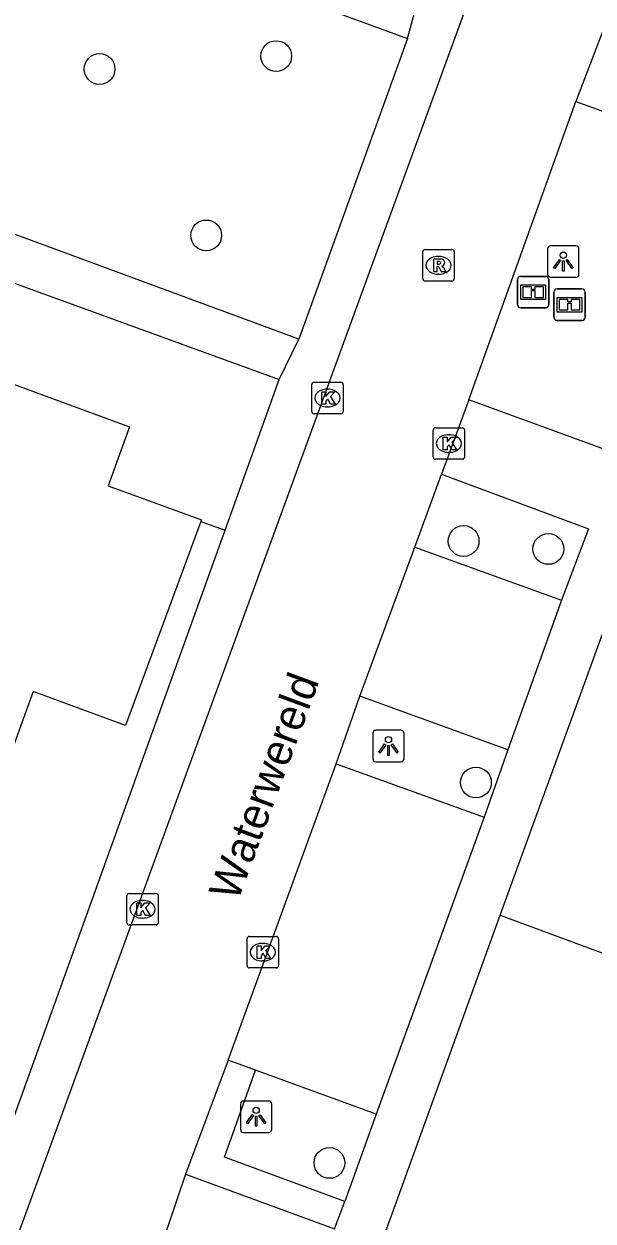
# Model space of a CAD drawing. Extents: x 155275 to 156263, y 382654 to 383635.
# Drawn here: x 155990.1 to 156008.18, y 383082.31 to 383120.33 of the extents above; entities that cross this region are included whole.
import ezdxf

# ---------------------------------------------------------------- set-up
doc = ezdxf.new("R2010")
doc.units = 0
for name, color, linetype in [('IMGEO_Boom', 7, 'Continuous'), ('IMGEO_Hek', 7, 'Continuous'), ('IMGEO_Informatiebord', 7, 'Continuous'), ('IMGEO_Kolk', 7, 'Continuous'), ('IMGEO_Lichtpunt', 7, 'Continuous'), ('IMGEO_Openbare_ruimte_label', 7, 'Continuous'), ('IMGEO_Pand', 7, 'Continuous'), ('IMGEO_Parkeervlak_open', 7, 'Continuous'), ('IMGEO_Rijbaan_lokaal_open', 7, 'Continuous'), ('IMGEO_Rioolput', 7, 'Continuous'), ('IMGEO_Voetpad_open', 7, 'Continuous')]:
    doc.layers.add(name, color=color, linetype=linetype)

msp = doc.modelspace()

# ---------------------------------------------------------------- linework, layer by layer
at = {"layer": 'IMGEO_Boom'}
for centre in [(155998.115, 383119.307), (155992.502, 383118.896), (155995.89, 383113.612), (156004.069, 383103.904), (156006.762, 383103.654), (156004.461, 383096.235), (155999.806, 383084.153)]:
    msp.add_circle(centre, 0.489, dxfattribs=at)
at = {"layer": 'IMGEO_Hek'}
for points in [[(155989.784, 383085.63), (155996.489, 383104.253)], [(155995.721, 383104.53), (155996.489, 383104.253)]]:
    msp.add_lwpolyline(points, dxfattribs=at)
at = {"layer": 'IMGEO_Informatiebord'}
for p, q in [((156005.787, 383111.411), (156005.787, 383112.211)), ((156005.787, 383112.211), (156005.787, 383111.411)), ((156005.887, 383112.311), (156006.677, 383112.311)), ((156006.677, 383112.311), (156005.887, 383112.311)), ((156006.777, 383112.211), (156006.777, 383111.411)), ((156006.777, 383111.411), (156006.777, 383112.211)), ((156006.937, 383111.011), (156006.937, 383111.811)), ((156006.937, 383111.811), (156006.937, 383111.011)), ((156007.037, 383111.911), (156007.827, 383111.911)), ((156007.827, 383111.911), (156007.037, 383111.911)), ((156007.927, 383111.811), (156007.927, 383111.011)), ((156007.927, 383111.011), (156007.927, 383111.811)), ((156006.677, 383111.311), (156005.887, 383111.311)), ((156005.887, 383111.311), (156006.677, 383111.311)), ((156007.827, 383110.911), (156007.037, 383110.911)), ((156007.037, 383110.911), (156007.827, 383110.911))]:
    msp.add_line(p, q, dxfattribs=at)
for points in [[(156005.888, 383112.043), (156006.676, 383112.043), (156006.676, 383111.579), (156005.888, 383111.579), (156005.888, 383112.043)], [(156005.953, 383111.978), (156005.953, 383111.644), (156006.228, 383111.644), (156006.229, 383111.857), (156006.333, 383111.858), (156006.334, 383111.644), (156006.611, 383111.644), (156006.611, 383111.978), (156006.335, 383111.978), (156006.335, 383111.898), (156006.229, 383111.898), (156006.229, 383111.978), (156005.953, 383111.978)], [(156007.038, 383111.643), (156007.826, 383111.643), (156007.826, 383111.179), (156007.038, 383111.179), (156007.038, 383111.643)], [(156007.103, 383111.578), (156007.103, 383111.244), (156007.378, 383111.244), (156007.379, 383111.457), (156007.483, 383111.458), (156007.484, 383111.244), (156007.761, 383111.244), (156007.761, 383111.578), (156007.485, 383111.578), (156007.485, 383111.498), (156007.379, 383111.498), (156007.379, 383111.578), (156007.103, 383111.578)]]:
    msp.add_lwpolyline(points, dxfattribs=at)
for centre, start, end in [((156005.887, 383112.211), 90, 180), ((156005.887, 383112.211), 90, 180), ((156006.677, 383112.211), 0, 90), ((156006.677, 383112.211), 360, 90), ((156007.037, 383111.811), 90, 180), ((156007.037, 383111.811), 90, 180), ((156007.827, 383111.811), 0, 90), ((156007.827, 383111.811), 360, 90), ((156005.887, 383111.411), 180, 270), ((156005.887, 383111.411), 180, 270), ((156006.677, 383111.411), 270, 0), ((156006.677, 383111.411), 270, 0), ((156007.037, 383111.011), 180, 270), ((156007.037, 383111.011), 180, 270), ((156007.827, 383111.011), 270, 0), ((156007.827, 383111.011), 270, 0)]:
    msp.add_arc(centre, 0.1, start, end, dxfattribs=at)
at = {"layer": 'IMGEO_Kolk'}
for p, q in [((155999.243, 383108.022), (155999.243, 383108.874)), ((155999.318, 383108.948), (156000.17, 383108.948)), ((155999.731, 383108.728), (155999.756, 383108.728)), ((156000.244, 383108.874), (156000.244, 383108.022)), ((155999.754, 383108.168), (155999.729, 383108.168)), ((156000.17, 383107.948), (155999.318, 383107.948)), ((156003.102, 383106.575), (156003.102, 383107.427)), ((156003.177, 383107.501), (156004.029, 383107.501)), ((156003.59, 383107.281), (156003.615, 383107.281)), ((156004.103, 383107.427), (156004.103, 383106.575)), ((156004.029, 383106.501), (156003.177, 383106.501)), ((156003.613, 383106.721), (156003.588, 383106.721)), ((155993.368, 383091.784), (155993.368, 383092.636)), ((155993.443, 383092.71), (155994.295, 383092.71)), ((155993.856, 383092.49), (155993.881, 383092.49)), ((155994.369, 383092.636), (155994.369, 383091.784)), ((155994.295, 383091.71), (155993.443, 383091.71)), ((155993.879, 383091.93), (155993.854, 383091.93)), ((155997.188, 383090.421), (155997.188, 383091.273)), ((155997.263, 383091.347), (155998.115, 383091.347)), ((155998.189, 383091.273), (155998.189, 383090.421)), ((155997.676, 383091.127), (155997.701, 383091.127)), ((155997.699, 383090.567), (155997.674, 383090.567)), ((155998.115, 383090.347), (155997.263, 383090.347))]:
    msp.add_line(p, q, dxfattribs=at)
for points in [[(155999.243, 383108.022), (155999.243, 383108.874)], [(155999.318, 383108.948), (156000.17, 383108.948)], [(156000.244, 383108.874), (156000.244, 383108.022)], [(155999.564, 383108.648), (155999.687, 383108.648), (155999.687, 383108.497), (155999.817, 383108.648), (155999.981, 383108.648), (155999.835, 383108.497), (155999.988, 383108.248), (155999.836, 383108.248), (155999.751, 383108.412), (155999.687, 383108.345), (155999.687, 383108.248), (155999.564, 383108.248), (155999.564, 383108.648)], [(156000.17, 383107.948), (155999.318, 383107.948)], [(156003.102, 383106.575), (156003.102, 383107.427)], [(156003.177, 383107.501), (156004.029, 383107.501)], [(156003.423, 383107.201), (156003.546, 383107.201), (156003.546, 383107.05), (156003.676, 383107.201), (156003.84, 383107.201), (156003.694, 383107.05), (156003.847, 383106.801), (156003.695, 383106.801), (156003.61, 383106.965), (156003.546, 383106.898), (156003.546, 383106.801), (156003.423, 383106.801), (156003.423, 383107.201)], [(156004.103, 383107.427), (156004.103, 383106.575)], [(156004.029, 383106.501), (156003.177, 383106.501)], [(155993.368, 383091.784), (155993.368, 383092.636)], [(155993.443, 383092.71), (155994.295, 383092.71)], [(155993.689, 383092.41), (155993.812, 383092.41), (155993.812, 383092.259), (155993.942, 383092.41), (155994.106, 383092.41), (155993.96, 383092.259), (155994.113, 383092.01), (155993.961, 383092.01), (155993.876, 383092.174), (155993.812, 383092.107), (155993.812, 383092.01), (155993.689, 383092.01), (155993.689, 383092.41)], [(155994.369, 383092.636), (155994.369, 383091.784)], [(155994.295, 383091.71), (155993.443, 383091.71)], [(155997.188, 383090.421), (155997.188, 383091.273)], [(155997.263, 383091.347), (155998.115, 383091.347)], [(155998.189, 383091.273), (155998.189, 383090.421)], [(155997.509, 383091.047), (155997.632, 383091.047), (155997.632, 383090.896), (155997.762, 383091.047), (155997.926, 383091.047), (155997.78, 383090.896), (155997.933, 383090.647), (155997.781, 383090.647), (155997.696, 383090.811), (155997.632, 383090.744), (155997.632, 383090.647), (155997.509, 383090.647), (155997.509, 383091.047)], [(155998.115, 383090.347), (155997.263, 383090.347)]]:
    msp.add_lwpolyline(points, dxfattribs=at)
for centre, start, end in [((155999.32, 383108.872), 91.552, 178.448), ((155999.32, 383108.872), 91.552, 178.448), ((156000.168, 383108.872), 1.552, 88.448), ((156000.168, 383108.872), 1.552, 88.448), ((155999.32, 383108.024), 181.552, 268.448), ((155999.32, 383108.024), 181.552, 268.448), ((156000.168, 383108.024), 271.552, 358.448), ((156000.168, 383108.024), 271.552, 358.448), ((156003.179, 383107.425), 91.552, 178.448), ((156003.179, 383107.425), 91.552, 178.448), ((156004.027, 383107.425), 1.552, 88.448), ((156004.027, 383107.425), 1.552, 88.448), ((156003.179, 383106.577), 181.552, 268.448), ((156003.179, 383106.577), 181.552, 268.448), ((156004.027, 383106.577), 271.552, 358.448), ((156004.027, 383106.577), 271.552, 358.448), ((155993.445, 383092.634), 91.552, 178.448), ((155993.445, 383092.634), 91.552, 178.448), ((155994.293, 383092.634), 1.552, 88.448), ((155994.293, 383092.634), 1.552, 88.448), ((155993.445, 383091.786), 181.552, 268.448), ((155993.445, 383091.786), 181.552, 268.448), ((155994.293, 383091.786), 271.552, 358.448), ((155994.293, 383091.786), 271.552, 358.448), ((155997.265, 383091.271), 91.552, 178.448), ((155997.265, 383091.271), 91.552, 178.448), ((155998.113, 383091.271), 1.552, 88.448), ((155998.113, 383091.271), 1.552, 88.448), ((155997.265, 383090.423), 181.552, 268.448), ((155997.265, 383090.423), 181.552, 268.448), ((155998.113, 383090.423), 271.552, 358.448), ((155998.113, 383090.423), 271.552, 358.448)]:
    msp.add_arc(centre, 0.0765, start, end, dxfattribs=at)
for centre, major_axis, ratio, start_param, end_param in [((155999.73, 383108.448), (-0.387, 0.002), 0.722429, 4.712389, 7.853982), ((155999.755, 383108.448), (-0.39, 0.002), 0.717154, 1.570796, 4.712389), ((156003.589, 383107.001), (-0.387, 0.002), 0.722429, 4.712389, 7.853982), ((156003.614, 383107.001), (-0.39, 0.002), 0.717154, 1.570796, 4.712389), ((155993.855, 383092.21), (-0.387, 0.002), 0.722429, 4.712389, 7.853982), ((155993.88, 383092.21), (-0.39, 0.002), 0.717154, 1.570796, 4.712389), ((155997.675, 383090.847), (-0.387, 0.002), 0.722429, 4.712389, 7.853982), ((155997.7, 383090.847), (-0.39, 0.002), 0.717154, 1.570796, 4.712389)]:
    msp.add_ellipse(centre, major_axis=major_axis, ratio=ratio, start_param=start_param, end_param=end_param, dxfattribs=at)
at = {"layer": 'IMGEO_Lichtpunt'}
for p, q in [((156006.738, 383113.185), (156006.738, 383112.378)), ((156006.738, 383113.185), (156006.738, 383112.378)), ((156007.64, 383113.28), (156006.832, 383113.28)), ((156007.64, 383113.28), (156006.832, 383113.28)), ((156007.734, 383112.378), (156007.734, 383113.185)), ((156007.734, 383112.378), (156007.734, 383113.185)), ((156006.832, 383112.284), (156007.64, 383112.284)), ((156006.832, 383112.284), (156007.64, 383112.284)), ((156001.184, 383097.798), (156001.184, 383096.991)), ((156001.184, 383097.798), (156001.184, 383096.991)), ((156002.086, 383097.893), (156001.278, 383097.893)), ((156002.086, 383097.893), (156001.278, 383097.893)), ((156002.18, 383096.991), (156002.18, 383097.798)), ((156002.18, 383096.991), (156002.18, 383097.798)), ((156001.278, 383096.897), (156002.086, 383096.897)), ((156001.278, 383096.897), (156002.086, 383096.897)), ((155996.979, 383086.023), (155996.979, 383085.216)), ((155996.979, 383086.023), (155996.979, 383085.216)), ((155997.881, 383086.118), (155997.073, 383086.118)), ((155997.881, 383086.118), (155997.073, 383086.118)), ((155997.975, 383085.216), (155997.975, 383086.023)), ((155997.975, 383085.216), (155997.975, 383086.023)), ((155997.073, 383085.122), (155997.881, 383085.122)), ((155997.073, 383085.122), (155997.881, 383085.122))]:
    msp.add_line(p, q, dxfattribs=at)
for points in [[(156007.112, 383112.849), (156007.151, 383112.821), (156006.963, 383112.559), (156006.925, 383112.586), (156007.112, 383112.849)], [(156007.214, 383112.801), (156007.261, 383112.801), (156007.261, 383112.479), (156007.214, 383112.479), (156007.214, 383112.801)], [(156007.324, 383112.821), (156007.362, 383112.848), (156007.549, 383112.586), (156007.51, 383112.558), (156007.324, 383112.821)], [(156001.558, 383097.462), (156001.597, 383097.434), (156001.409, 383097.172), (156001.371, 383097.199), (156001.558, 383097.462)], [(156001.66, 383097.414), (156001.707, 383097.414), (156001.707, 383097.092), (156001.66, 383097.092), (156001.66, 383097.414)], [(156001.77, 383097.434), (156001.808, 383097.461), (156001.995, 383097.199), (156001.956, 383097.171), (156001.77, 383097.434)], [(155997.353, 383085.687), (155997.392, 383085.659), (155997.204, 383085.397), (155997.166, 383085.424), (155997.353, 383085.687)], [(155997.455, 383085.639), (155997.502, 383085.639), (155997.502, 383085.317), (155997.455, 383085.317), (155997.455, 383085.639)], [(155997.565, 383085.659), (155997.603, 383085.686), (155997.79, 383085.424), (155997.751, 383085.396), (155997.565, 383085.659)]]:
    msp.add_lwpolyline(points, dxfattribs=at)
for centre in [(156007.237, 383112.983), (156001.683, 383097.596), (155997.478, 383085.821)]:
    msp.add_circle(centre, 0.0994, dxfattribs=at)
for centre, start, end in [((156006.832, 383113.185), 90, 180), ((156006.832, 383113.185), 90, 180), ((156007.64, 383113.185), 0, 90), ((156007.64, 383113.185), 0, 90), ((156006.832, 383112.378), 180, 270), ((156006.832, 383112.378), 180, 270), ((156007.64, 383112.378), 270, 0), ((156007.64, 383112.378), 270, 360), ((156001.278, 383097.798), 90, 180), ((156001.278, 383097.798), 90, 180), ((156002.086, 383097.798), 0, 90), ((156002.086, 383097.798), 0, 90), ((156001.278, 383096.991), 180, 270), ((156001.278, 383096.991), 180, 270), ((156002.086, 383096.991), 270, 0), ((156002.086, 383096.991), 270, 360), ((155997.073, 383086.023), 90, 180), ((155997.073, 383086.023), 90, 180), ((155997.881, 383086.023), 0, 90), ((155997.881, 383086.023), 0, 90), ((155997.073, 383085.216), 180, 270), ((155997.073, 383085.216), 180, 270), ((155997.881, 383085.216), 270, 0), ((155997.881, 383085.216), 270, 360)]:
    msp.add_arc(centre, 0.0946, start, end, dxfattribs=at)
at = {"layer": 'IMGEO_Pand'}
for points in [[(155979.66, 383087.889), (155987.596, 383109.681), (155993.457, 383107.535), (155992.772, 383105.655), (155995.741, 383104.583), (155995.721, 383104.53), (155993.324, 383098.048), (155990.395, 383099.131), (155989.529, 383096.753), (155989.516, 383096.719), (155986.709, 383097.75), (155984.093, 383090.587)], [(156005.226, 383092.022), (156008.872, 383102.022)], [(156005.226, 383092.022), (156011.215, 383089.811), (156014.882, 383099.825), (156008.872, 383102.022)]]:
    msp.add_lwpolyline(points, dxfattribs=at)
at = {"layer": 'IMGEO_Parkeervlak_open'}
for points in [[(156002.522, 383103.705), (156007.184, 383102.028)], [(156005.471, 383097.271), (156000.773, 383098.977)], [(156000.015, 383096.833), (156004.724, 383095.14)], [(156001.287, 383085.698), (155997.459, 383087.098)]]:
    msp.add_lwpolyline(points, dxfattribs=at)
at = {"layer": 'IMGEO_Rijbaan_lokaal_open'}
for points in [[(155978.27, 383049.91), (155978.483, 383050.407), (155986.615, 383072.853), (155988.629, 383078.321), (155989.904, 383081.846), (156015.13, 383150.933), (156019.183, 383149.44)], [(156008.546, 383120.25), (156007.639, 383117.862)], [(156004.235, 383108.392), (156007.639, 383117.862)], [(156004.235, 383108.392), (156003.364, 383106.031)], [(156002.522, 383103.705), (156003.364, 383106.031)], [(156000.773, 383098.977), (156002.522, 383103.705)], [(156000.015, 383096.833), (156000.773, 383098.977)], [(155996.587, 383087.419), (156000.015, 383096.833)], [(155996.587, 383087.419), (155995.232, 383083.796)], [(155995.232, 383083.796), (155994.679, 383082.17), (155994.016, 383080.34), (155992.747, 383076.842)]]:
    msp.add_lwpolyline(points, dxfattribs=at)
at = {"layer": 'IMGEO_Rioolput'}
for p, q in [((156002.771, 383112.236), (156002.771, 383113.088)), ((156002.846, 383113.162), (156003.698, 383113.162)), ((156003.259, 383112.942), (156003.284, 383112.942)), ((156003.772, 383113.088), (156003.772, 383112.236)), ((156003.698, 383112.162), (156002.846, 383112.162)), ((156003.282, 383112.382), (156003.257, 383112.382))]:
    msp.add_line(p, q, dxfattribs=at)
for points in [[(156002.771, 383112.236), (156002.771, 383113.088)], [(156002.846, 383113.162), (156003.698, 383113.162)], [(156003.772, 383113.088), (156003.772, 383112.236)], [(156003.36, 383112.86), (156003.108, 383112.862), (156003.108, 383112.462)], [(156003.108, 383112.462), (156003.232, 383112.462), (156003.232, 383112.624), (156003.243, 383112.624)], [(156003.286, 383112.781), (156003.232, 383112.781), (156003.232, 383112.7)], [(156003.232, 383112.7), (156003.284, 383112.7)], [(156003.29, 383112.595), (156003.361, 383112.462), (156003.501, 383112.462), (156003.436, 383112.588)], [(156003.698, 383112.162), (156002.846, 383112.162)]]:
    msp.add_lwpolyline(points, dxfattribs=at)
for centre, radius, start, end in [((156002.848, 383113.086), 0.0765, 91.552, 178.448), ((156002.848, 383113.086), 0.0765, 91.552, 178.448), ((156003.696, 383113.086), 0.0765, 1.552, 88.448), ((156003.696, 383113.086), 0.0765, 1.552, 88.448), ((156003.242, 383112.571), 0.0533, 26.0293, 88.6989), ((156003.268, 383112.889), 0.19, 274.7715, 282.9687), ((156003.292, 383112.685), 0.0964, 77.0061, 93.1865), ((156003.306, 383112.742), 0.0378, 276.6634, 79.6772), ((156003.359, 383112.75), 0.109, 350.3612, 89.416), ((156003.357, 383112.75), 0.112, 277.5842, 350.9817), ((156003.341, 383112.535), 0.108, 29.5134, 73.7905), ((156002.848, 383112.238), 0.0765, 181.552, 268.448), ((156002.848, 383112.238), 0.0765, 181.552, 268.448), ((156003.696, 383112.238), 0.0765, 271.552, 358.448), ((156003.696, 383112.238), 0.0765, 271.552, 358.448)]:
    msp.add_arc(centre, radius, start, end, dxfattribs=at)
for centre, major_axis, ratio, start_param, end_param in [((156003.258, 383112.662), (-0.387, 0.002), 0.722429, 4.712389, 7.853982), ((156003.283, 383112.662), (-0.39, 0.002), 0.717154, 1.570796, 4.712389)]:
    msp.add_ellipse(centre, major_axis=major_axis, ratio=ratio, start_param=start_param, end_param=end_param, dxfattribs=at)
at = {"layer": 'IMGEO_Voetpad_open'}
for points in [[(155935.166, 383133.515), (155934.688, 383132.207), (155940.754, 383129.934), (155998.212, 383109.04)], [(155998.834, 383110.312), (155983.613, 383115.932), (155986.932, 383125.484), (156002.283, 383119.87)], [(156002.283, 383119.87), (156002.636, 383121.155)], [(156002.283, 383119.87), (155998.834, 383110.312)], [(156007.639, 383117.862), (156012.321, 383116.179), (156008.909, 383106.684), (156004.235, 383108.392)], [(155998.212, 383109.04), (155998.834, 383110.312)], [(155989.784, 383085.63), (155996.489, 383104.253), (155998.212, 383109.04)], [(156003.364, 383106.031), (156008.039, 383104.29), (156007.184, 383102.028)], [(156007.184, 383102.028), (156005.471, 383097.271)], [(156005.471, 383097.271), (156004.724, 383095.14)], [(156004.724, 383095.14), (156001.287, 383085.698)], [(156000.865, 383079.959), (156005.226, 383092.022)], [(156000.293, 383082.929), (155996.469, 383084.337), (155997.459, 383087.098)], [(155997.459, 383087.098), (155996.587, 383087.419)], [(156001.287, 383085.698), (156000.293, 383082.929)], [(155995.232, 383083.796), (155999.963, 383082.064), (156000.293, 383082.929)]]:
    msp.add_lwpolyline(points, dxfattribs=at)

# ---------------------------------------------------------------- texts
at = {"layer": 'IMGEO_Openbare_ruimte_label'}
msp.add_text('Waterwereld', height=1, rotation=69.6988, dxfattribs=at).set_placement((155996.89, 383092.427))

doc.saveas('drawing.dxf')
